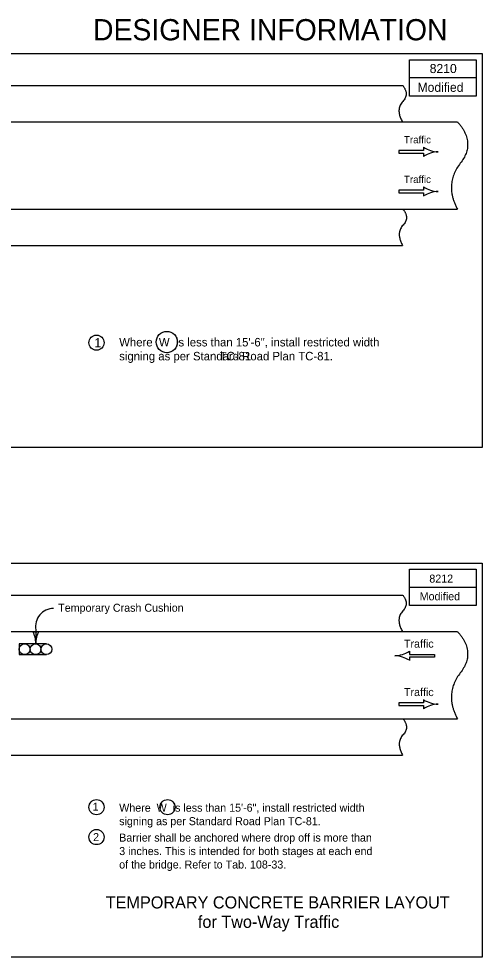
# Model space of a CAD drawing. Extents: x 8045 to 81668, y 6217 to 16762.
# Drawn here: x 16087 to 16853, y 6217 to 7766 of the extents above; entities that cross this region are included whole.
import ezdxf

# ---------------------------------------------------------------- set-up
doc = ezdxf.new("R2010")
doc.units = 0
for name, color, linetype in [('dsnNonPlotable', 7, 'Continuous'), ('dsnShtPlotShapeBatchPrint', 7, 'Continuous'), ('dsnStdBlockModified', 7, 'Continuous'), ('dsnStdBorder', 7, 'Continuous'), ('dsnStdLineWork', 7, 'Continuous'), ('Level 1', 7, 'Continuous'), ('Level 2', 7, 'Continuous'), ('Level 3', 7, 'Continuous'), ('Level 5', 7, 'Continuous')]:
    doc.layers.add(name, color=color, linetype=linetype)

msp = doc.modelspace()

# ---------------------------------------------------------------- linework, layer by layer
at = {"layer": 'dsnNonPlotable'}
for p, q in [((15372.7, 7655.5), (16721.1, 7655.5)), ((15480.2, 7595.5), (16811.5, 7595.5)), ((16755.8, 7548.3), (16714.6, 7548.3)), ((16714.6, 7548.3), (16714.6, 7543.8)), ((16714.6, 7543.8), (16755.8, 7543.8)), ((16755.8, 7553.6), (16755.8, 7548.3)), ((16755.8, 7543.8), (16755.8, 7538.6)), ((16779.8, 7546.1), (16779.8, 7546.1)), ((16755.8, 7482.9), (16714.6, 7482.9)), ((16714.6, 7482.9), (16714.6, 7478.4)), ((16714.6, 7478.4), (16755.8, 7478.4)), ((16755.8, 7488.1), (16755.8, 7482.9)), ((16755.8, 7478.4), (16755.8, 7473.1)), ((16779.8, 7480.6), (16779.8, 7480.6)), ((15342.7, 7451.5), (16811.5, 7451.5)), ((15372.7, 7391.5), (16721.1, 7391.5))]:
    msp.add_line(p, q, dxfattribs=at)
for centre, radius in [((16331.9, 7232.3), 17.6), ((16215.8, 7231.2), 12.5)]:
    msp.add_circle(centre, radius, dxfattribs=at)
for centre, start, end in [((16781.7, 7594.4), 237.618, 267.648), ((16781.7, 7497.7), 92.352, 122.382), ((16781.7, 7528.9), 237.618, 267.648), ((16781.7, 7432.3), 92.352, 122.382)]:
    msp.add_arc(centre, 48.4, start, end, dxfattribs=at)
for points in [[(16721.1, 7655.5), (16732.9, 7641.4), (16709.3, 7616.3), (16720.7, 7595.5)], [(16811.5, 7595.5), (16842.9, 7561), (16789.6, 7493), (16811.5, 7451.5)], [(16721.6, 7451.4), (16733.4, 7437.3), (16709.8, 7412.3), (16721.1, 7391.5)]]:
    msp.add_open_spline(points, degree=2, dxfattribs=at)
at = {"layer": 'dsnShtPlotShapeBatchPrint'}
msp.add_lwpolyline([(16842.5, 7698), (16842.5, 7638), (16732.5, 7638), (16732.5, 7698), (16842.5, 7698), (16842.5, 7668), (16732.5, 7668)], dxfattribs=at)
at = {"layer": 'dsnStdBlockModified'}
for p, q in [((13747.5, 7708), (16852.5, 7708)), ((16852.5, 7708), (16852.5, 7058))]:
    msp.add_line(p, q, dxfattribs=at)
at = {"layer": 'dsnStdBorder'}
msp.add_line((16852.5, 7058), (13747.5, 7058), dxfattribs=at)
at = {"layer": 'dsnStdLineWork'}
for p, q in [((13747.5, 6867.4), (16852.5, 6867.4)), ((16852.5, 6867.4), (16852.5, 6217.4)), ((15372.7, 6814.8), (16721.1, 6814.8)), ((15342.7, 6754.8), (16811.5, 6754.8)), ((16115.6, 6757.4), (16115.6, 6734.9)), ((16089.4, 6722.2), (16088.1, 6721.9)), ((16133.2, 6734.5), (16088.2, 6734.5)), ((16088.2, 6734.5), (16088.2, 6716.5)), ((16732.2, 6722.1), (16732.2, 6716.9)), ((16087.6, 6718.5), (16087.6, 6718.5)), ((16088.2, 6716.5), (16133.2, 6716.5)), ((16708.3, 6714.6), (16708.3, 6714.6)), ((16732.2, 6716.9), (16773.5, 6716.9)), ((16773.5, 6712.4), (16732.2, 6712.4)), ((16732.2, 6712.4), (16732.2, 6707.1)), ((16773.5, 6716.9), (16773.5, 6712.4)), ((16755.8, 6642.3), (16755.8, 6637)), ((16755.8, 6637), (16714.6, 6637)), ((16714.6, 6637), (16714.6, 6632.5)), ((16714.6, 6632.5), (16755.8, 6632.5)), ((16755.8, 6632.5), (16755.8, 6627.3)), ((16779.8, 6634.8), (16779.8, 6634.8)), ((15342.7, 6610.8), (16811.5, 6610.8)), ((15372.7, 6550.8), (16721.1, 6550.8)), ((16852.5, 6217.4), (13747.5, 6217.4))]:
    msp.add_line(p, q, dxfattribs=at)
msp.add_lwpolyline([(16842.5, 6857.4), (16842.5, 6797.4), (16732.5, 6797.4), (16732.5, 6857.4), (16842.5, 6857.4), (16842.5, 6827.4), (16732.5, 6827.4)], dxfattribs=at)
for centre, radius in [((16097.2, 6725.5), 9), ((16097.2, 6725.5), 9), ((16115.2, 6725.5), 9), ((16115.2, 6725.5), 9), ((16133.2, 6725.5), 9), ((16133.2, 6725.5), 9), ((16215.8, 6464.8), 12.5), ((16333.1, 6464.8), 12.5), ((16215.8, 6415.6), 12.5)]:
    msp.add_circle(centre, radius, dxfattribs=at)
for centre, radius, start, end in [((16145.1, 6762.8), 30, 90, 190.3537), ((16115.6, 6770.5), 16.4, 252.2666, 287.7334), ((16073.1, 6734.9), 42.5, 0, 28.0725), ((16158.1, 6734.9), 42.5, 151.9275, 180), ((16706.3, 6763), 48.4, 272.352, 302.382), ((16706.3, 6666.3), 48.4, 57.618, 87.648), ((16781.7, 6683.1), 48.4, 237.618, 267.648), ((16781.7, 6586.5), 48.4, 92.352, 122.382)]:
    msp.add_arc(centre, radius, start, end, dxfattribs=at)
for points in [[(16721.1, 6814.8), (16732.9, 6800.7), (16709.3, 6775.7), (16720.7, 6754.8)], [(16811.5, 6754.8), (16842.9, 6720.3), (16789.6, 6652.3), (16811.5, 6610.8)], [(16721.6, 6610.7), (16733.4, 6596.6), (16709.8, 6571.6), (16721.1, 6550.8)]]:
    msp.add_open_spline(points, degree=2, dxfattribs=at)
at = {"layer": 'Level 2'}
msp.add_line((16852.5, 7708), (16852.5, 7708), dxfattribs=at)

# ---------------------------------------------------------------- texts
at = {"layer": 'dsnStdLineWork'}
for s, height, p in [('8212', 13.2, (16765.2, 6835.4)), ('Modified', 13.2, (16749.3, 6806.2)), ('Temporary Crash Cushion', 13.2, (16152.6, 6787.3)), ('Traffic', 13.2, (16723.3, 6728)), ('Traffic', 13.2, (16723.3, 6648.2)), ('1', 13.2, (16209.5, 6459.1)), ('Where  W  is less than 15\'-6", install restricted width', 13.2, (16253.3, 6457.4)), ('signing as per Standard Road Plan TC-81.', 13.2, (16253.3, 6435.2)), ('2', 13.2, (16210.2, 6409)), ('Barrier shall be anchored where drop off is more than ', 13.2, (16253.3, 6408.1)), ('3 inches. This is intended for both stages at each end ', 13.2, (16253.3, 6385.9)), ('of the bridge. Refer to Tab. 108-33.', 13.2, (16253.3, 6363.7)), ('TEMPORARY CONCRETE BARRIER LAYOUT', 20, (16231.1, 6297.8)), ('for Two-Way Traffic', 20, (16383.2, 6265.8))]:
    msp.add_text(s, height=height, dxfattribs=at).set_placement(p)
at = {"layer": 'Level 1'}
msp.add_text('DESIGNER INFORMATION', height=35, dxfattribs=at).set_placement((16210.1, 7730))
at = {"layer": 'Level 3'}
for s, p in [('8210', (16765.8, 7676)), ('Modified', (16745.7, 7645))]:
    msp.add_text(s, height=15, dxfattribs=at).set_placement(p)
at = {"layer": 'Level 5'}
for s, height, p in [('Traffic', 12, (16723.3, 7560.1)), ('Traffic', 12, (16723.3, 7494.6)), ('1', 15, (16212.4, 7223.7)), ('Where  W  is less than 15\'-6", install restricted width', 14, (16253.3, 7225)), ('signing as per Standard Road Plan TC-81.', 14, (16253.3, 7202)), ('                                TC-81', 14, (16252.6, 7202))]:
    msp.add_text(s, height=height, dxfattribs=at).set_placement(p)

doc.saveas('drawing.dxf')
